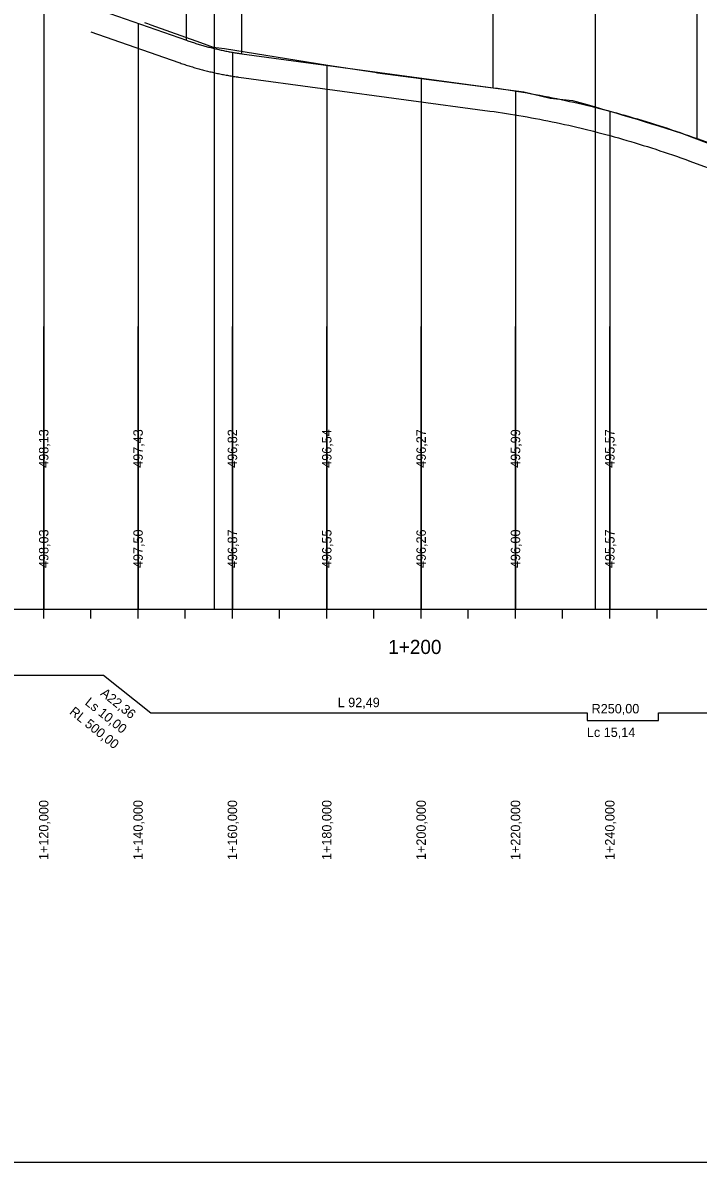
# Model space of a CAD drawing. Extents: x -632716 to -629545, y -1094726 to -1088285.
# Drawn here: x -631495.2 to -631352, y -1093689.1 to -1093447.3 of the extents above; entities that cross this region are included whole.
import ezdxf

# ---------------------------------------------------------------- set-up
doc = ezdxf.new("R2010")
doc.units = 0
for name, color, linetype in [('20', 7, 'Continuous'), ('Default', 7, 'Continuous'), ('formát', 7, 'Continuous'), ('NIVELETA_VYSKY', 7, 'Continuous'), ('PŘÍKOP', 7, 'Continuous'), ('REZ_POPIS', 7, 'Continuous'), ('REZ_TABULKA', 7, 'Continuous'), ('REZ_TENKA', 7, 'Continuous'), ('REZ_TLUSTA', 7, 'Continuous'), ('SKLONY_NIVELETA', 7, 'Continuous'), ('TECNY_NIVELETA', 7, 'Continuous'), ('TEREN_VYSKY', 7, 'Continuous'), ('VOZOVKA', 7, 'Continuous')]:
    doc.layers.add(name, color=color, linetype=linetype)

msp = doc.modelspace()

# ---------------------------------------------------------------- linework, layer by layer
at = {"layer": '20'}
for points in [[(-631490.75, -1093440.44), (-631490.75, -1093521.74), (-631490.75, -1093571.74), (-631490.75, -1093511.74)], [(-631470.75, -1093447.44), (-631470.75, -1093521.74), (-631470.75, -1093571.74), (-631470.75, -1093511.74)], [(-631450.75, -1093453.58), (-631450.75, -1093521.74), (-631450.75, -1093571.74), (-631450.75, -1093511.74)], [(-631430.75, -1093456.33), (-631430.75, -1093521.74), (-631430.75, -1093571.74), (-631430.75, -1093511.74)], [(-631410.75, -1093459.04), (-631410.75, -1093521.74), (-631410.75, -1093571.74), (-631410.75, -1093511.74)], [(-631390.75, -1093461.81), (-631390.75, -1093521.74), (-631390.75, -1093571.74), (-631390.75, -1093511.74)], [(-631370.75, -1093466.07), (-631370.75, -1093521.74), (-631370.75, -1093571.74), (-631370.75, -1093511.74)]]:
    msp.add_lwpolyline(points, dxfattribs=at)
at = {"layer": 'Default'}
for p, q in [((-631506.42, -1093434.96), (-631460.47, -1093451.04)), ((-631506.42, -1093434.96), (-631460.47, -1093451.04)), ((-631448.75, -1093453.89), (-631395.48, -1093461.11)), ((-631448.75, -1093453.89), (-631395.48, -1093461.11)), ((-631352.26, -1093471.9), (-631296.85, -1093492.07)), ((-631352.26, -1093471.9), (-631296.85, -1093492.07))]:
    msp.add_line(p, q, dxfattribs=at)
for points in [[(-631460.47, -1093451.04), (-631460.22, -1093451.13), (-631459.98, -1093451.21), (-631459.73, -1093451.29), (-631459.49, -1093451.38), (-631459.25, -1093451.46), (-631459, -1093451.54), (-631458.76, -1093451.61), (-631458.51, -1093451.69), (-631458.27, -1093451.77), (-631458.03, -1093451.84), (-631457.78, -1093451.92), (-631457.54, -1093451.99), (-631457.29, -1093452.06), (-631457.05, -1093452.13), (-631456.8, -1093452.2), (-631456.56, -1093452.27), (-631456.32, -1093452.34), (-631456.07, -1093452.4), (-631455.83, -1093452.47), (-631455.58, -1093452.53), (-631455.34, -1093452.6), (-631455.1, -1093452.66), (-631454.85, -1093452.72), (-631454.36, -1093452.84), (-631454.12, -1093452.89), (-631453.88, -1093452.95), (-631453.63, -1093453.01), (-631453.39, -1093453.06), (-631453.14, -1093453.11), (-631452.9, -1093453.17), (-631452.66, -1093453.22), (-631452.41, -1093453.27), (-631452.17, -1093453.32), (-631451.92, -1093453.36), (-631451.68, -1093453.41), (-631451.44, -1093453.46), (-631451.19, -1093453.5), (-631450.95, -1093453.54), (-631450.7, -1093453.59), (-631450.46, -1093453.63), (-631450.22, -1093453.67), (-631449.97, -1093453.71), (-631449.73, -1093453.75), (-631449.48, -1093453.78), (-631449.24, -1093453.82), (-631449, -1093453.85), (-631448.75, -1093453.89)], [(-631460.47, -1093451.04), (-631460.22, -1093451.13), (-631459.98, -1093451.21), (-631459.73, -1093451.29), (-631459.49, -1093451.38), (-631459.25, -1093451.46), (-631459, -1093451.54), (-631458.76, -1093451.61), (-631458.51, -1093451.69), (-631458.27, -1093451.77), (-631458.03, -1093451.84), (-631457.78, -1093451.92), (-631457.54, -1093451.99), (-631457.29, -1093452.06), (-631457.05, -1093452.13), (-631456.8, -1093452.2), (-631456.56, -1093452.27), (-631456.32, -1093452.34), (-631456.07, -1093452.4), (-631455.83, -1093452.47), (-631455.58, -1093452.53), (-631455.34, -1093452.6), (-631455.1, -1093452.66), (-631454.85, -1093452.72), (-631454.36, -1093452.84), (-631454.12, -1093452.89), (-631453.88, -1093452.95), (-631453.63, -1093453.01), (-631453.39, -1093453.06), (-631453.14, -1093453.11), (-631452.9, -1093453.17), (-631452.66, -1093453.22), (-631452.41, -1093453.27), (-631452.17, -1093453.32), (-631451.92, -1093453.36), (-631451.68, -1093453.41), (-631451.44, -1093453.46), (-631451.19, -1093453.5), (-631450.95, -1093453.54), (-631450.7, -1093453.59), (-631450.46, -1093453.63), (-631450.22, -1093453.67), (-631449.97, -1093453.71), (-631449.73, -1093453.75), (-631449.48, -1093453.78), (-631449.24, -1093453.82), (-631449, -1093453.85), (-631448.75, -1093453.89)], [(-631395.48, -1093461.11), (-631394.58, -1093461.23), (-631393.68, -1093461.36), (-631392.78, -1093461.49), (-631391.88, -1093461.63), (-631390.98, -1093461.77), (-631390.08, -1093461.91), (-631389.18, -1093462.06), (-631388.28, -1093462.22), (-631387.38, -1093462.38), (-631386.48, -1093462.54), (-631385.58, -1093462.71), (-631384.68, -1093462.88), (-631383.78, -1093463.05), (-631382.88, -1093463.23), (-631381.97, -1093463.42), (-631381.07, -1093463.61), (-631380.17, -1093463.8), (-631379.27, -1093464), (-631378.37, -1093464.2), (-631377.47, -1093464.4), (-631376.57, -1093464.61), (-631375.67, -1093464.83), (-631374.77, -1093465.05), (-631372.97, -1093465.5), (-631372.07, -1093465.73), (-631371.17, -1093465.96), (-631370.27, -1093466.2), (-631369.37, -1093466.45), (-631368.47, -1093466.7), (-631367.57, -1093466.95), (-631366.67, -1093467.21), (-631365.77, -1093467.47), (-631364.86, -1093467.73), (-631363.96, -1093468), (-631363.06, -1093468.28), (-631362.16, -1093468.55), (-631361.26, -1093468.84), (-631360.36, -1093469.12), (-631359.46, -1093469.42), (-631358.56, -1093469.71), (-631357.66, -1093470.01), (-631356.76, -1093470.32), (-631355.86, -1093470.62), (-631354.96, -1093470.94), (-631354.06, -1093471.25), (-631353.16, -1093471.58), (-631352.26, -1093471.9)], [(-631395.48, -1093461.11), (-631394.58, -1093461.23), (-631393.68, -1093461.36), (-631392.78, -1093461.49), (-631391.88, -1093461.63), (-631390.98, -1093461.77), (-631390.08, -1093461.91), (-631389.18, -1093462.06), (-631388.28, -1093462.22), (-631387.38, -1093462.38), (-631386.48, -1093462.54), (-631385.58, -1093462.71), (-631384.68, -1093462.88), (-631383.78, -1093463.05), (-631382.88, -1093463.23), (-631381.97, -1093463.42), (-631381.07, -1093463.61), (-631380.17, -1093463.8), (-631379.27, -1093464), (-631378.37, -1093464.2), (-631377.47, -1093464.4), (-631376.57, -1093464.61), (-631375.67, -1093464.83), (-631374.77, -1093465.05), (-631372.97, -1093465.5), (-631372.07, -1093465.73), (-631371.17, -1093465.96), (-631370.27, -1093466.2), (-631369.37, -1093466.45), (-631368.47, -1093466.7), (-631367.57, -1093466.95), (-631366.67, -1093467.21), (-631365.77, -1093467.47), (-631364.86, -1093467.73), (-631363.96, -1093468), (-631363.06, -1093468.28), (-631362.16, -1093468.55), (-631361.26, -1093468.84), (-631360.36, -1093469.12), (-631359.46, -1093469.42), (-631358.56, -1093469.71), (-631357.66, -1093470.01), (-631356.76, -1093470.32), (-631355.86, -1093470.62), (-631354.96, -1093470.94), (-631354.06, -1093471.25), (-631353.16, -1093471.58), (-631352.26, -1093471.9)]]:
    msp.add_lwpolyline(points, dxfattribs=at)
at = {"layer": 'formát'}
msp.add_lwpolyline([(-632715.96, -1093689.05), (-630764.61, -1093689.05), (-630764.61, -1093095.05), (-632715.96, -1093095.05)], close=True, dxfattribs=at)
at = {"layer": 'PŘÍKOP'}
for p, q in [((-631480.75, -1093449.24), (-631462.12, -1093455.76)), ((-631449.42, -1093458.84), (-631396.15, -1093466.06)), ((-631353.97, -1093476.6), (-631298.56, -1093496.76))]:
    msp.add_line(p, q, dxfattribs=at)
for points in [[(-631462.11, -1093455.77), (-631461.85, -1093455.85), (-631461.59, -1093455.94), (-631461.33, -1093456.03), (-631461.07, -1093456.12), (-631460.8, -1093456.21), (-631460.54, -1093456.29), (-631460.28, -1093456.38), (-631460.01, -1093456.46), (-631459.75, -1093456.54), (-631459.49, -1093456.62), (-631459.22, -1093456.7), (-631458.96, -1093456.78), (-631458.69, -1093456.86), (-631458.43, -1093456.94), (-631458.17, -1093457.01), (-631457.9, -1093457.09), (-631457.64, -1093457.16), (-631457.37, -1093457.23), (-631457.11, -1093457.3), (-631456.85, -1093457.37), (-631456.58, -1093457.44), (-631456.32, -1093457.51), (-631456.05, -1093457.57), (-631455.53, -1093457.7), (-631455.26, -1093457.76), (-631454.99, -1093457.82), (-631454.73, -1093457.88), (-631454.46, -1093457.94), (-631454.2, -1093458), (-631453.94, -1093458.06), (-631453.67, -1093458.11), (-631453.41, -1093458.17), (-631453.14, -1093458.22), (-631452.87, -1093458.27), (-631452.61, -1093458.32), (-631452.34, -1093458.37), (-631452.08, -1093458.42), (-631451.81, -1093458.47), (-631451.55, -1093458.51), (-631451.28, -1093458.56), (-631451.02, -1093458.6), (-631450.75, -1093458.65), (-631450.49, -1093458.69), (-631450.22, -1093458.73), (-631449.96, -1093458.77), (-631449.69, -1093458.8), (-631449.43, -1093458.84)], [(-631396.17, -1093466.06), (-631395.28, -1093466.18), (-631394.4, -1093466.31), (-631393.52, -1093466.44), (-631392.64, -1093466.57), (-631391.77, -1093466.71), (-631390.89, -1093466.85), (-631390.01, -1093467), (-631389.13, -1093467.15), (-631388.26, -1093467.3), (-631387.38, -1093467.46), (-631386.5, -1093467.62), (-631385.62, -1093467.79), (-631384.74, -1093467.96), (-631383.87, -1093468.14), (-631382.99, -1093468.31), (-631382.11, -1093468.5), (-631381.23, -1093468.69), (-631380.35, -1093468.88), (-631379.47, -1093469.08), (-631378.6, -1093469.28), (-631377.72, -1093469.48), (-631376.84, -1093469.69), (-631375.97, -1093469.9), (-631374.2, -1093470.34), (-631373.32, -1093470.57), (-631372.44, -1093470.8), (-631371.57, -1093471.03), (-631370.69, -1093471.27), (-631369.81, -1093471.51), (-631368.93, -1093471.76), (-631368.05, -1093472.01), (-631367.17, -1093472.27), (-631366.29, -1093472.52), (-631365.41, -1093472.79), (-631364.53, -1093473.06), (-631363.65, -1093473.33), (-631362.77, -1093473.6), (-631361.89, -1093473.89), (-631361.01, -1093474.17), (-631360.13, -1093474.46), (-631359.25, -1093474.75), (-631358.37, -1093475.05), (-631357.49, -1093475.35), (-631356.61, -1093475.66), (-631355.73, -1093475.97), (-631354.85, -1093476.28), (-631353.96, -1093476.6)]]:
    msp.add_lwpolyline(points, dxfattribs=at)
at = {"layer": 'REZ_TABULKA'}
msp.add_lwpolyline([(-631522.14, -1093585.74), (-631478.06, -1093585.74), (-631478.06, -1093585.74), (-631468.06, -1093593.74), (-631468.06, -1093593.74), (-631375.56, -1093593.74), (-631375.56, -1093595.34), (-631360.42, -1093595.34), (-631360.42, -1093593.74), (-631247.21, -1093593.74), (-631247.21, -1093595.34), (-631241.62, -1093595.34), (-631241.62, -1093593.74), (-631195.85, -1093593.74)], dxfattribs=at)
at = {"layer": 'REZ_TENKA'}
for p, q in [((-631490.75, -1093573.74), (-631490.75, -1093571.74)), ((-631480.75, -1093573.74), (-631480.75, -1093571.74)), ((-631470.75, -1093573.74), (-631470.75, -1093571.74)), ((-631460.75, -1093573.74), (-631460.75, -1093571.74)), ((-631450.75, -1093573.74), (-631450.75, -1093571.74)), ((-631440.75, -1093573.74), (-631440.75, -1093571.74)), ((-631430.75, -1093573.74), (-631430.75, -1093571.74)), ((-631420.75, -1093573.74), (-631420.75, -1093571.74)), ((-631400.75, -1093573.74), (-631400.75, -1093571.74)), ((-631390.75, -1093573.74), (-631390.75, -1093571.74)), ((-631380.75, -1093573.74), (-631380.75, -1093571.74)), ((-631370.75, -1093573.74), (-631370.75, -1093571.74)), ((-631360.75, -1093573.74), (-631360.75, -1093571.74))]:
    msp.add_line(p, q, dxfattribs=at)
at = {"layer": 'REZ_TLUSTA'}
for p, q in [((-631410.75, -1093573.74), (-631410.75, -1093569.74)), ((-632610.75, -1093571.74), (-631190.75, -1093571.74))]:
    msp.add_line(p, q, dxfattribs=at)
at = {"layer": 'SKLONY_NIVELETA'}
for p, q in [((-631454.61, -1093353.09), (-631454.61, -1093571.74)), ((-631373.87, -1093364.03), (-631373.87, -1093571.74)), ((-631506.42, -1093434.96), (-631460.47, -1093451.04)), ((-631448.75, -1093453.89), (-631395.48, -1093461.11)), ((-631352.26, -1093471.9), (-631296.85, -1093492.07))]:
    msp.add_line(p, q, dxfattribs=at)
for points in [[(-631460.47, -1093451.04), (-631460.22, -1093451.13), (-631459.98, -1093451.21), (-631459.73, -1093451.29), (-631459.49, -1093451.38), (-631459.25, -1093451.46), (-631459, -1093451.54), (-631458.76, -1093451.61), (-631458.51, -1093451.69), (-631458.27, -1093451.77), (-631458.03, -1093451.84), (-631457.78, -1093451.92), (-631457.54, -1093451.99), (-631457.29, -1093452.06), (-631457.05, -1093452.13), (-631456.8, -1093452.2), (-631456.56, -1093452.27), (-631456.32, -1093452.34), (-631456.07, -1093452.4), (-631455.83, -1093452.47), (-631455.58, -1093452.53), (-631455.34, -1093452.6), (-631455.1, -1093452.66), (-631454.85, -1093452.72), (-631454.36, -1093452.84), (-631454.12, -1093452.89), (-631453.88, -1093452.95), (-631453.63, -1093453.01), (-631453.39, -1093453.06), (-631453.14, -1093453.11), (-631452.9, -1093453.17), (-631452.66, -1093453.22), (-631452.41, -1093453.27), (-631452.17, -1093453.32), (-631451.92, -1093453.36), (-631451.68, -1093453.41), (-631451.44, -1093453.46), (-631451.19, -1093453.5), (-631450.95, -1093453.54), (-631450.7, -1093453.59), (-631450.46, -1093453.63), (-631450.22, -1093453.67), (-631449.97, -1093453.71), (-631449.73, -1093453.75), (-631449.48, -1093453.78), (-631449.24, -1093453.82), (-631449, -1093453.85), (-631448.75, -1093453.89)], [(-631395.48, -1093461.11), (-631394.58, -1093461.23), (-631393.68, -1093461.36), (-631392.78, -1093461.49), (-631391.88, -1093461.63), (-631390.98, -1093461.77), (-631390.08, -1093461.91), (-631389.18, -1093462.06), (-631388.28, -1093462.22), (-631387.38, -1093462.38), (-631386.48, -1093462.54), (-631385.58, -1093462.71), (-631384.68, -1093462.88), (-631383.78, -1093463.05), (-631382.88, -1093463.23), (-631381.97, -1093463.42), (-631381.07, -1093463.61), (-631380.17, -1093463.8), (-631379.27, -1093464), (-631378.37, -1093464.2), (-631377.47, -1093464.4), (-631376.57, -1093464.61), (-631375.67, -1093464.83), (-631374.77, -1093465.05), (-631372.97, -1093465.5), (-631372.07, -1093465.73), (-631371.17, -1093465.96), (-631370.27, -1093466.2), (-631369.37, -1093466.45), (-631368.47, -1093466.7), (-631367.57, -1093466.95), (-631366.67, -1093467.21), (-631365.77, -1093467.47), (-631364.86, -1093467.73), (-631363.96, -1093468), (-631363.06, -1093468.28), (-631362.16, -1093468.55), (-631361.26, -1093468.84), (-631360.36, -1093469.12), (-631359.46, -1093469.42), (-631358.56, -1093469.71), (-631357.66, -1093470.01), (-631356.76, -1093470.32), (-631355.86, -1093470.62), (-631354.96, -1093470.94), (-631354.06, -1093471.25), (-631353.16, -1093471.58), (-631352.26, -1093471.9)]]:
    msp.add_lwpolyline(points, dxfattribs=at)
at = {"layer": 'TECNY_NIVELETA'}
for p, q in [((-631460.47, -1093451.04), (-631460.47, -1093350.04)), ((-631448.75, -1093453.89), (-631448.75, -1093352.89)), ((-631395.48, -1093461.11), (-631395.48, -1093360.11)), ((-631352.26, -1093471.9), (-631352.26, -1093370.9))]:
    msp.add_line(p, q, dxfattribs=at)
at = {"layer": 'VOZOVKA'}
msp.add_lwpolyline([(-631469.39, -1093447.26), (-631468.72, -1093447.5), (-631468.06, -1093447.74), (-631457.5, -1093451.5), (-631454.85, -1093452.47), (-631452.46, -1093452.79), (-631430.5, -1093456.32), (-631420.53, -1093457.83), (-631420.25, -1093457.87), (-631420.03, -1093457.93), (-631388.95, -1093461.98), (-631383.37, -1093463.29), (-631378.68, -1093463.79), (-631375.56, -1093464.68), (-631374.05, -1093465.11), (-631372.54, -1093465.55), (-631371.02, -1093466), (-631369.51, -1093466.45), (-631367.99, -1093466.9), (-631366.48, -1093467.35), (-631364.96, -1093467.81), (-631363.45, -1093468.28), (-631361.93, -1093468.75), (-631360.42, -1093469.22), (-631355.54, -1093470.74), (-631324.52, -1093482.51)], dxfattribs=at)

# ---------------------------------------------------------------- texts
at = {"layer": 'NIVELETA_VYSKY'}
for s, p in [('498,13', (-631489.75, -1093541.74)), ('497,43', (-631469.75, -1093541.74)), ('496,82', (-631449.75, -1093541.74)), ('496,54', (-631429.75, -1093541.74)), ('496,27', (-631409.75, -1093541.74)), ('495,99', (-631389.75, -1093541.74)), ('495,57', (-631369.75, -1093541.74))]:
    msp.add_text(s, height=2, rotation=90, dxfattribs=at).set_placement(p)
at = {"layer": 'REZ_POPIS'}
msp.add_text('1+200', height=3, dxfattribs=at).set_placement((-631417.71, -1093581.24))
at = {"layer": 'REZ_TABULKA'}
for s, rotation, p in [('Ls 10,00', 321.3402, (-631482.16, -1093591.83)), ('A22,36', 321.3402, (-631478.87, -1093589.85)), ('RL 500,00', 321.3402, (-631485.45, -1093593.81)), ('1+120,000', 90, (-631489.75, -1093624.95)), ('1+140,000', 90, (-631469.75, -1093624.95)), ('1+160,000', 90, (-631449.75, -1093624.95)), ('1+180,000', 90, (-631429.75, -1093624.95)), ('1+200,000', 90, (-631409.75, -1093624.95)), ('1+220,000', 90, (-631389.75, -1093624.95)), ('1+240,000', 90, (-631369.75, -1093624.95))]:
    msp.add_text(s, height=2, rotation=rotation, dxfattribs=at).set_placement(p)
for s, p in [('L 92,49', (-631428.44, -1093592.52)), ('R250,00', (-631374.61, -1093593.84)), ('Lc 15,14', (-631375.61, -1093598.84))]:
    msp.add_text(s, height=2, dxfattribs=at).set_placement(p)
at = {"layer": 'TEREN_VYSKY'}
for s, p in [('498,03', (-631489.75, -1093563)), ('497,50', (-631469.75, -1093563)), ('496,87', (-631449.75, -1093563)), ('496,55', (-631429.75, -1093563)), ('496,26', (-631409.75, -1093563)), ('496,00', (-631389.75, -1093563)), ('495,57', (-631369.75, -1093563))]:
    msp.add_text(s, height=2, rotation=90, dxfattribs=at).set_placement(p)

doc.saveas('drawing.dxf')
